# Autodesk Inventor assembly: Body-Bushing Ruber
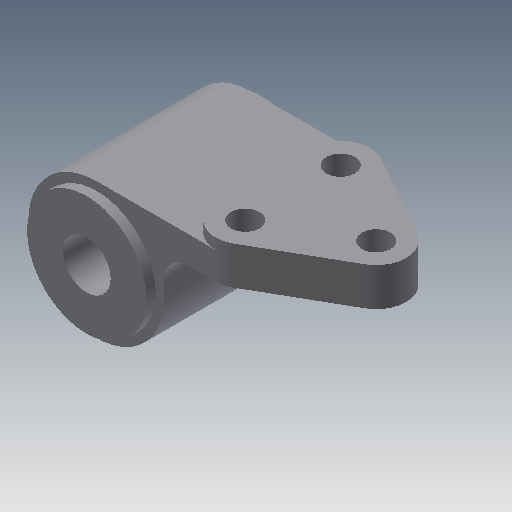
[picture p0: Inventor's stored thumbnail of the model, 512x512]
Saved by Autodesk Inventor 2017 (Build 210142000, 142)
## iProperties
Created: 2011-07
Part Number: Body-Bushing Ruber
Document SubType Name: Assembly
Designer: CadCim
Author: CadCim
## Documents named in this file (3)
- D:\New folder\New folder (3)\Inventor_2016_tut\c09_Inv_tut_2016\c09_tut03_inv\Anti Vibration Mount\Body-Bushing Ruber.iam
- D:\New folder\New folder (3)\Inventor_2016_tut\c09_Inv_tut_2016\c09_tut03_inv\Anti Vibration Mount\Body.ipt
- D:\New folder\New folder (3)\Inventor_2016_tut\c09_Inv_tut_2016\c09_tut03_inv\Anti Vibration Mount\Bushing Rubber.ipt
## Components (3 placed, 2 different names)
1. Body:1 — Insert:1, Insert:2
2. Bushing Rubber:1 — Insert:1
3. Bushing Rubber:2 — Insert:2
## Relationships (2: Insert 2)
- Insert:1: Body:1 ↔ Bushing Rubber:1
- Insert:2: Body:1 ↔ Bushing Rubber:2
